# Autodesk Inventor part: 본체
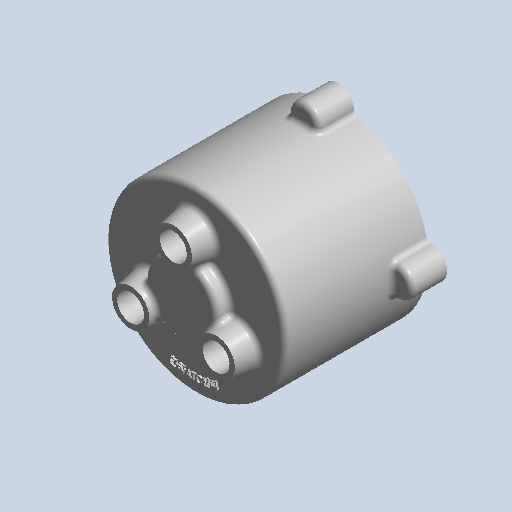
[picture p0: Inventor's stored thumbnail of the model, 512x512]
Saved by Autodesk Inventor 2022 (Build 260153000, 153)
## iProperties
Created: 2021-07
Part Number: 본체
Document SubType Name: 모델링
Designer: mdu
Material: 알루미늄 6061
Density: 1 g/cm^3
Appearance: 알루미늄 - 평지
변환 표준: STEP AP214IS
파일 이름: C:\Users\SeoGD\Desktop\?쒗뿕\紐몄껜.stp
전처리기: Build: 253, Release: 2010 SP1 - Date: Wed 07/29/2009
전송 단위: 밀리미터
불확실성: 0.01
Author: mdu
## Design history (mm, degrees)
sketch "스케치2"
  geometry: C1 r 50 at (0, 0); 1 further point
  constraints: 1 centre point, 1 coincident
  dimensions: "d9" = 100 diameter of C1
extrude "돌출2" new body sketch "스케치2" distance "d10" = 80; taper "d11" = 0 deg
feature "쉘1" dims "d12" = 5
sketch "스케치3" dims "d13" = 55
  geometry: C1 r 7.5 at (0, 27.5); C2 r 12.5 at (0, 27.5); 2 further points
  constraints: 2 centre point, 2 coincident, 2 vertical alignment, 2 other
  dimensions: "d14" = 15 diameter of C1; "d15" = 25 diameter of C2
extrude "돌출3" join sketch "스케치3" distance "d16" = 12; taper "d17" = -10 deg
sketch "스케치4"
  geometry: L1 (0, 0)-(0, 88); L2 (0, 70)-(14, 70); L3 (-45, 75)-(45, 75) reference; L4 (-50, 80)-(50, 80) reference; L5 (14, 70)-(14, 75); L6 (20, 80)-(20, 88); L7 (20, 88)-(0, 88); L8 (20, 80)-(14, 75)
  constraints: 12 end point, 3 point on line, 2 perpendicular, 1 vertical
  dimensions: "d34" = 40 diameter of L6 L1; "d35" = 90 deg angle of L5 L3; "d36" = 5 distance between parallel lines of L2 L3; "d37" = 8 distance between parallel lines of L7 L4; "d51" = 28 diameter of L5.end L1
revolve "회전1" sketch "스케치4" stored, may be unused: angle "d38" = 90 deg
hole "구멍3" diameter "d41" = 15; stored, may be unused: countersink angle "d45" = 90 deg, drill point angle "d47" = 0 deg; dims "d39" = 10, "d40" = 10, "d42" = 6, "d43" = 22, "d44" = 13, "d46" = 15
chamfer "모따기2" distance "d48" = 1; stored, may be unused: second distance "d49" = 2, angle "d50" = 45 deg
fillet "모깎기4" dims "d78" = 3
hole "구멍2" diameter "d20" = 15; stored, may be unused: countersink angle "d24" = 90 deg, drill point angle "d26" = 118 deg; dims "d21" = 6, "d22" = 25, "d23" = 1, "d25" = 15, "d76" = 10, "d77" = 10
chamfer "모따기1" distance "d27" = 1; stored, may be unused: second distance "d28" = 2, angle "d29" = 45 deg
sketch "스케치9"
  geometry: C1 r 12.5 at (0, 0) reference; C2 r 12.5 at (-23.816, -41.25) reference; C3 r 12.5 at (23.816, -41.25) reference; 1 further point
extrude "돌출5" cut sketch "스케치9" extent not by distance; stored distance "d79" = 10; taper "d80" = 0 deg
fillet "모깎기1" dims "d52" = 3
fillet "모깎기2" dims "d53" = 3, "d72" = 0.2
sketch "스케치5"
  geometry: A1 r 50 centre (0, 0) between (50, 0) and (-8.074, 49.344) reference; A2 r 8.5 centre (0, 52) between (8.074, 49.344) and (-8.074, 49.344); 1 further point
  constraints: 5 point on circle, 1 centre point, 1 horizontal alignment
  dimensions: "d54" = 90 deg dimension on point (0, 0) A2.centre A1.start; "d55" = 52 distance of A2.centre point (0, 0); "d56" = 17 diameter of A2
extrude "돌출4" join sketch "스케치5" distance "d57" = 20; taper "d58" = 0 deg
fillet "모깎기3" dims "d59" = 3
hole "구멍4" diameter "d62" = 4.134; stored, may be unused: countersink angle "d66" = 90 deg, drill point angle "d68" = 118 deg; dims "d60" = 10, "d61" = 10, "d63" = 12, "d64" = 22, "d65" = 13, "d67" = 15
sketch "스케치6"
  geometry: C1 r 47 at (0, 0) reference; C2 r 42.5 at (0, 0); 1 further point
  constraints: 1 centre point, 1 coincident, 1 other
  dimensions: "d73" = 85 diameter of C2
feature "엠보싱1" sketch "스케치6" dims "d34" = 40, "d35" = 90 deg, "d36" = 5, "d37" = 8, "d51" = 28, "d74" = 1, "d75" = 0
node "솔리드1"
node "솔리드 본체"
node "곡면 본체"
pattern_circular "원형 패턴1" dims angle "d31" = 360 deg
pattern_circular "원형 패턴2" dims angle "d70" = 360 deg
node "솔리드2"
